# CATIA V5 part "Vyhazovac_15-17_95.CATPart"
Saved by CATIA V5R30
Part number: Vyhazovac_15-17/95
Nomenclature: E1010/15-17/95
Description: MEUSBURGER
Property "Material": "1.7131"
Publications: "DrillHole", "Base"
Bounding box of the stored display mesh (mm): x -12.298 to 12.298, y -12.297 to 12.297, z 0 to 112
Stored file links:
  E:\Bakalarka\Model\Forma_v7\Vyhazovac_15-17_95.CATPart
  E:\dev\MoldDesign\intel_a\startup\components\MoldCatalog\LeaderPin\Meusburger\LeaderPin_E1010\TableE1010.txt
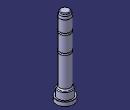
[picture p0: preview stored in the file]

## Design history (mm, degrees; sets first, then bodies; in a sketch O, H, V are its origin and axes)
Parameters
  Ref = "E1010/15-17/95" {design table}
  L1 = 17 mm {design table}
  L2 = 95 mm {design table}
  L3 = 6 mm {design table}
  L4 = 5 mm {design table}
  L5 = 25 mm {design table}
  L6 = 50 mm {design table}
  L7 = 0 mm {design table}
  L8 = 0 mm {design table}
  L11 = 2.4 mm {design table}
  L12 = 8.5 mm {design table}
  L13 = 2.5 mm {design table}
  D1 = 20 mm {design table}
  D2 = 15 mm {design table}
  D3 = 24.6 mm {design table}
  D4 = 14.6 mm {design table}
  D5 = 14.2 mm {design table}
  R = 1 mm {design table}
  R1 = 15 mm {design table}
  R3 = 1.8 mm {design table}
  R4 = 2 mm {design table}
  R5 = 1 mm {design table}
  F = 0.3 mm {design table}
  W = 15 deg {design table}
  X = 5.5 mm {design table}
  L0 = 112 mm {design table}
  k_d3 = 26 mm {design table}
  k_l3 = 6.3 mm {design table}
  Mat = "1.7131" {design table}
  HeatTreat = "60HRC" {design table}
  SupplierRef = "Meusburger 2017"
  BmpRef = "F_MldLeaderPin_D2_L"
  D = 15 mm {= D2}
  ThL = 17 mm {= L1}
  ThD = 24.6 mm {= D3}
  DrillHole_Length = 225 mm
  L = 95 mm {= L2}
Fillet1: radius 1.8 {= R3}, on edge [face of Shaft1 from Sketch1.L5 | face of Shaft1 from Sketch1.L4]
Set1 "BaseBody"
  Point1 "Base": (0, 0, 0)
  Plane1: type Offset, RefPlane xy-plane, Offset 225 {= DrillHole_Length}, reversed
Body1 "PartBody" (main body)
  Sketch1 on zx-plane, origin (0, 0, 0), H (1, 0, 0), V (0, 0, -1)
    point P1 (0, 0)
    line L1 (0, 0) -> (12.3, 0)
    line L2 (12.3, 0) -> (12.3, -6)
    line L3 (12.3, -6) -> (10, -6)
    point P4 (10, -6)
    point P5 (10, -17)
    line L4 (10, -17) -> (7.5, -17)
    point P6 (7.5, -17)
    point P7 (7.5, -17)
    line L5 (7.5, -17) -> (7.5, -107)
    line L6 (7.5, -107) -> (6.1603, -112)
    line L7 (6.1603, -112) -> (0, -112)
    point P10 (0, -112)
    point P11 (0, -112)
    axis line L8 (0, -112) -> (0, 0)
    point P12 (0, 0)
    point P13 (10, -6)
    line L9 (10, -6) -> (10, -17)
    point P14 (10, -17)
    point P15 (10, -17)
    point P16 (10, -17)
    angle L5 L6 = 15 {= W}
    distance L5 L8 = 7.5 {= D2 /2}
    distance L4 L7 = 95 {= L2}
    distance L2 L8 = 12.3 {= D3 /2}
    length L2 = 6 {= L3}
    distance L1 L4 = 17 {= L1}
    length L6 V = 5 {= L4}
    distance L9 L8 = 10 {= D1 /2}
    coincidence: L8 P10, L8 V, H L1, P1 O, P12 H, P11 L7, P13 P4, P14 P5, L4 P5, L9 P14, P7 P6, P15 P16
    vertical: L2 V, L9 V
    horizontal: L1 H, L4 H, L7 H, L3 H
  Shaft1: profile Sketch1, axis Sketch1.L8, angle 360
  Sketch2 on zx-plane, origin (0, 0, 0), H (-1, 0, 0), V (0, 0, 1)
    arc A1 centre (9.1, 87) radius 2 from (7.5, 88.2) to (7.5, 85.8) ccw
    point P1 (7.1, 87)
    construction line L1 (7.1, 87) -> (11.1, 87)
    point P2 (9.1, 87)
    point P3 (11.1, 87)
    point P4 (-7.1, 87)
    point P5 (-11.1, 87)
    construction line L2 (-7.1, 87) -> (-11.1, 87)
    point P7 (-11.1, 87)
    point P8 (-11.1, 87)
    construction circle A2 centre (-9.1, 87) radius 2
    line L3 (7.5, 88.2) -> (7.5, 85.8)
    radius A1 = 2 {= deleted_LENGTH}
    distance L1 H = 87 {= L1+L2-L5}
    distance P4 P1 = 14.2 {= D5}
    distance L3 V = 7.5 {= D2/2}
    coincidence: P1 A1, P2 L1, P5 A2, P7 P8, P7 P5
    horizontal: L1 H
    symmetry: P1 P4 V, P3 P5 V, L1 L2 V, A1 A2 V
    vertical: L3 V
  Groove1: profile Sketch2, axis Sketch2.V, angle 360
  Sketch3 on zx-plane, origin (0, 0, 0), H (-1, 0, 0), V (0, 0, 1)
    arc A1 centre (9.1, 62) radius 2 from (7.5, 63.2) to (7.5, 60.8) ccw
    point P1 (7.1, 62)
    construction line L1 (7.1, 62) -> (9.1, 62)
    point P2 (9.1, 62)
    point P3 (7.5, 60.8)
    point P4 (7.5, 63.2)
    point P5 (9.1, 62)
    point P6 (-7.1, 62)
    point P7 (-9.1, 62)
    construction line L2 (-7.1, 62) -> (-9.1, 62)
    point P8 (-9.1, 62)
    point P9 (-7.5, 60.8)
    point P10 (-7.5, 63.2)
    construction arc A2 centre (-9.1, 62) radius 2 from (-7.5, 63.2) to (-7.5, 60.8) cw
    line L3 (7.5, 63.2) -> (7.5, 60.8)
    radius A1 = 2 {= deleted_LENGTH}
    distance L1 H = 62 {= L1+L2-L6}
    distance P6 P1 = 14.2 {= D5}
    distance L3 V = 7.5 {= D2/2}
    coincidence: P1 A1, P2 L1, P7 P8
    horizontal: L1 H
    symmetry: P1 P6 V, P5 P7 V, L1 L2 V, P3 P9 V, P4 P10 V, A1 A2 V
    vertical: L3 V
  Groove2: profile Sketch3, axis Sketch3.V, angle 360
  Sketch4 on zx-plane, origin (0, 0, 0), H (-1, 0, 0), V (0, 0, 1)
    arc A1 centre (17.5, 141) radius 2 from (16, 142.3229) to (16, 139.6771) ccw
    point P1 (15.5, 141)
    construction line L1 (15.5, 141) -> (17.5, 141)
    point P2 (17.5, 141)
    point P3 (16, 142.3229)
    point P4 (16, 139.6771)
    point P5 (17.5, 141)
    point P6 (-15.5, 141)
    point P7 (-17.5, 141)
    construction line L2 (-15.5, 141) -> (-17.5, 141)
    point P9 (-16, 142.3229)
    point P10 (-16, 139.6771)
    construction arc A2 centre (-17.5, 141) radius 2 from (-16, 142.3229) to (-16, 139.6771) cw
    line L3 (16, 142.3229) -> (16, 139.6771)
    radius A1 = 2 {= deleted_LENGTH}
    distance L1 H = 112 {= L1+L2-L7}
    distance P6 P1 = 14.2 {= D5}
    distance L3 V = 7.5 {= D2/2}
    coincidence: P1 A1, P2 L1, P5 P2
    horizontal: L1 H
    symmetry: P1 P6 V, P5 P7 V, L1 L2 V, P3 P9 V, P4 P10 V, A1 A2 V
    vertical: L3 V
  Groove3: profile Sketch4, axis Sketch4.V, angle 360, deactivated
  Sketch5 on zx-plane, origin (0, 0, 0), H (-1, 0, 0), V (0, 0, 1)
    arc A1 centre (17.5, 141) radius 2 from (16, 142.3229) to (16, 139.6771) ccw
    point P1 (15.5, 141)
    construction line L1 (15.5, 141) -> (17.5, 141)
    point P2 (17.5, 141)
    point P3 (16, 142.3229)
    point P4 (16, 139.6771)
    point P5 (17.5, 141)
    point P6 (-15.5, 141)
    point P7 (-17.5, 141)
    construction line L2 (-15.5, 141) -> (-17.5, 141)
    point P9 (-16, 142.3229)
    point P10 (-16, 139.6771)
    construction arc A2 centre (-17.5, 141) radius 2 from (-16, 142.3229) to (-16, 139.6771) cw
    line L3 (16, 142.3229) -> (16, 139.6771)
    radius A1 = 2 {= deleted_LENGTH}
    distance L1 H = 112 {= L1+L2-L8}
    distance P6 P1 = 14.2 {= D5}
    distance L3 V = 7.5 {= D2/2}
    coincidence: P1 A1, P2 L1, P5 P2
    horizontal: L1 H
    symmetry: P1 P6 V, P5 P7 V, L1 L2 V, P3 P9 V, P4 P10 V, A1 A2 V
    vertical: L3 V
  Groove4: profile Sketch5, axis Sketch5.V, angle 360, deactivated
  Chamfer1: length 0.3 {= F}, angle 45, on edge [face of Shaft1 from Sketch1.L3 | face of Shaft1 from Sketch1.L2]; edge [face of Shaft1 from Sketch1.L2 | face of Shaft1 from Sketch1.L1]
  Fillet2: radius 15 {= R1}, on edge [face of Shaft1 from Sketch1.L6 | face of Shaft1 from Sketch1.L5]
  Fillet3: radius 1 {= R}, on edge [face of Shaft1 from Sketch1.L7 | face of Shaft1 from Sketch1.L6]
  Fillet4: radius 1, on edge [face of Shaft1 from Sketch1.L4 | face of Shaft1 from Sketch1.L9]
Body2 "DrillHole"
  Sketch6 on Plane1, origin (0, 0, -225), H (1, 0, 0), V (0, 1, 0)
    point P1 (0, 0)
    reference projected point E1 (0, 0) from Point1
    coincidence: E1 P1
  Hole1: placed by Sketch6, at (0, 0, -225) direction (0, 0, 1), diameter 20 {= D1}, depth 337 {= DrillHole_Length +L1+L2}, counterbore diameter 26 {= k_d3}, counterbore depth 231 {= DrillHole_Length +L3}
Relations
  design table "TableE1010", configuration 50, drives Ref, L1, L2, L3, L4, L5, L6, L7, L8, L11, L12, L13, D1, D2, D3, D4, D5, R, R1, R3, R4, R5, F, W, X, L0, k_d3, k_l3, Mat, HeatTreat
  rule "Groove_activity":
    if L5==0mm
    {
    	Groove1.Activity = false
    	Sketch2.Activity = false
    }
    else
    {
    	Groove1.Activity = true
    	Sketch2.Activity = true
    }
    if L6==0mm
    {
    	Groove2.Activity = false
    	Sketch3.Activity = false
    }
    else
    {
    	Groove2.Activity = true
    	Sketch3.Activity = true
    }
    if L7==0mm
    {
    	Groove3.Activity = false
    	Sketch4.Activity = false
    }
    else
    {
    	Groove3.Activity = true
    	Sketch4.Activity = true
    }
    if L8==0mm
    {
    	Groove4.Activity = false
    	Sketch5.Activity = false
    }
    else
    {
    	Groove4.Activity = true
    	Sketch5.Activity = true
    }
  rule "Radius_Rule":
    If R5 == 0mm
    {
    	Fillet4.Radius  = 0.1mm
    	Fillet4.Activity  = false
    }
    else
    {
    	Fillet4.Radius  = R5
    	Fillet4.Activity  = true
    }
